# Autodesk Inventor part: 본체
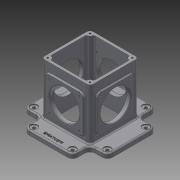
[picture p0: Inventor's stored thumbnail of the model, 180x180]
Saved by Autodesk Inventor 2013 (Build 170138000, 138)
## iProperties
Created: 2018-09
Part Number: 본체
Material: 알루미늄 6061
Document SubType Name: Modeling
Designer: mduedu
Density: 2.71 g/cm^3
Mass: 1126.64 g
Surface Area: 1144.86 cm^2
Volume: 415.736 cm^3
Author: mduedu
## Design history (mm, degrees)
sketch "스케치1"
  geometry: L1 (90, 52.5)-(-90, 52.5); L2 (-90, 52.5)-(-90, -52.5); L3 (-90, -52.5)-(90, -52.5); L4 (90, -52.5)-(90, 52.5); L5 (90, 52.5)-(-90, -52.5); L6 (-90, 52.5)-(90, -52.5); L7 (-52.5, -90)-(52.5, -90); L8 (52.5, -90)-(52.5, 90); L9 (52.5, 90)-(-52.5, 90); L10 (-52.5, 90)-(-52.5, -90); L11 (-52.5, -90)-(52.5, 90); L12 (52.5, -90)-(-52.5, 90); 1 further point
  constraints: 24 end point, 4 midpoint, 4 parallel, 2 horizontal, 2 perpendicular
  dimensions: "d0" = 180 distance of L3.end L2.end; "d1" = 105 distance of L2.end L1.end; "d105" = 105 distance of L9.end L8.end; "d106" = 180 distance of L8.end L7.end
extrude "돌출1" new body sketch "스케치1" distance "d2" = 10; taper "d3" = 0 deg
fillet "모깎기16" dims "d107" = 11
sketch "스케치2"
  geometry: L1 (-52.5, -52.5)-(52.5, -52.5); L2 (52.5, -52.5)-(52.5, 52.5); L3 (52.5, 52.5)-(-52.5, 52.5); L4 (-52.5, 52.5)-(-52.5, -52.5); L5 (-52.5, -52.5)-(52.5, 52.5); L6 (52.5, -52.5)-(-52.5, 52.5); 1 further point
  constraints: 12 end point, 2 midpoint, 2 parallel, 1 horizontal, 1 perpendicular
  dimensions: "d4" = 105 distance of L3.end L2.end; "d5" = 105 distance of L2.end L1.end
extrude "돌출2" join sketch "스케치2" distance "d6" = 110; taper "d7" = 0 deg
sketch "스케치14"
  geometry: L1 (-52.5, 52.5)-(52.5, 52.5) reference; L2 (52.5, 52.5)-(52.5, -52.5) reference; L3 (52.5, -52.5)-(-52.5, -52.5) reference; L4 (-52.5, -52.5)-(-52.5, 52.5) reference; L5 (46.5, 46.5)-(-46.5, 46.5); L6 (-46.5, 46.5)-(-46.5, -46.5); L7 (-46.5, -46.5)-(46.5, -46.5); L8 (46.5, -46.5)-(46.5, 46.5); 1 further point
  constraints: 8 end point, 3 other
  dimensions: "d85" = 6 distance between parallel lines of L5 L1
extrude "돌출10" cut sketch "스케치14" stored distance "d86" = 10; taper "d87" = 0 deg
fillet "모깎기1" dims "d12" = 7
sketch "스케치15"
  geometry: A1 r 7 centre (-45.5, 45.5) between (-45.5, 52.5) and (-52.5, 45.5) reference; A2 r 7 centre (45.5, 45.5) between (52.5, 45.5) and (45.5, 52.5) reference; A3 r 7 centre (45.5, -45.5) between (45.5, -52.5) and (52.5, -45.5) reference; A4 r 7 centre (-45.5, -45.5) between (-52.5, -45.5) and (-45.5, -52.5) reference; 5 further points
  constraints: 4 coincident, 4 vertical alignment, 8 other
extrude "돌출11" join sketch "스케치15" stored distance "d88" = 10; taper "d89" = 0 deg
fillet "모깎기15" dims "d90" = 3
sketch "스케치6"
  geometry: L1 (50, 20)-(130, 20); L2 (130, 20)-(130, 100); L3 (130, 100)-(50, 100); L4 (50, 100)-(50, 20); L5 (50, 20)-(130, 100); L6 (130, 20)-(50, 100); L7 (0, 0)-(180, 0) reference; 4 further points
  constraints: 12 end point, 4 midpoint, 2 parallel, 1 horizontal, 1 perpendicular, 1 vertical alignment
  dimensions: "d25" = 80 distance of L3.end L2.end; "d26" = 80 distance of L2.end L1.end; "d27" = 60 distance of point (90, 0) point (90, 60)
extrude "돌출6" join sketch "스케치6" distance "d28" = 3; taper "d29" = 0 deg
fillet "모깎기7" dims "d30" = 8
sketch "스케치7"
  geometry: C1 r 32.5 at (90, 60); 1 further point
  constraints: 1 centre point, 1 vertical alignment
  dimensions: "d32" = 65 diameter of C1; "d33" = 60 distance of C1.centre point (90, 0)
extrude "돌출7" cut sketch "스케치7" stored distance "d34" = 3; taper "d35" = 0 deg
fillet "모깎기9" dims "d36" = 3
sketch "스케치8"
  geometry: L1 (5.5, 10)-(85.5, 10); L2 (85.5, 10)-(85.5, 90); L3 (85.5, 90)-(5.5, 90); L4 (5.5, 90)-(5.5, 10); L5 (5.5, 10)-(85.5, 90); L6 (85.5, 10)-(5.5, 90); L7 (-7, -10)-(98, -10) reference; C1 r 32.5 at (45.5, 50); 4 further points
  constraints: 12 end point, 4 midpoint, 2 parallel, 1 centre point, 1 coincident, 1 horizontal, 1 perpendicular, 1 vertical alignment
  dimensions: "d37" = 80 distance of L3.end L2.end; "d38" = 80 distance of L2.end L1.end; "d39" = 60 distance from line of point (45.5, 50) L7; "d40" = 65 diameter of C1
extrude "돌출8" join sketch "스케치8" distance "d41" = 3; taper "d42" = 0 deg
fillet "모깎기10" dims "d43" = 8
extrude "돌출9" cut sketch "스케치8" stored distance "d44" = 3; taper "d45" = 0 deg
fillet "모깎기11" dims "d46" = 3
sketch "스케치9"
  geometry: L1 (50, 92)-(50, 28) reference; L2 (58, 20)-(122, 20) reference; L3 (130, 28)-(130, 92) reference; L4 (122, 100)-(58, 100) reference; C1 r 32.5 at (90, 60) reference; A1 r 8 centre (58, 92) between (58, 100) and (50, 92) reference; A2 r 8 centre (58, 28) between (50, 28) and (58, 20) reference; A3 r 8 centre (122, 28) between (122, 20) and (130, 28) reference; A4 r 8 centre (122, 92) between (130, 92) and (122, 100) reference; 5 further points
  constraints: 4 coincident
hole "구멍1" sketch "스케치9" at (58, 92), (122, 92), (122, 28), (58, 28) diameter "d47" = 3.242; stored, may be unused: countersink angle "d51" = 90 deg, drill point angle "d53" = 118 deg; dims "d48" = 6, "d49" = 4, "d50" = 2, "d52" = 9
sketch "스케치10"
  geometry: L1 (13.5, 10)-(77.5, 10) reference; L2 (85.5, 18)-(85.5, 82) reference; L3 (77.5, 90)-(13.5, 90) reference; L4 (5.5, 82)-(5.5, 18) reference; C1 r 32.5 at (45.5, 50) reference; A1 r 8 centre (13.5, 18) between (5.5, 18) and (13.5, 10) reference; A2 r 8 centre (77.5, 18) between (77.5, 10) and (85.5, 18) reference; A3 r 8 centre (77.5, 82) between (85.5, 82) and (77.5, 90) reference; A4 r 8 centre (13.5, 82) between (13.5, 90) and (5.5, 82) reference; 5 further points
  constraints: 4 coincident
hole "구멍2" sketch "스케치10" at (13.5, 82), (77.5, 82), (77.5, 18), (13.5, 18) diameter "d54" = 3.242; stored, may be unused: countersink angle "d58" = 90 deg, drill point angle "d60" = 118 deg; dims "d55" = 6, "d56" = 4, "d57" = 2, "d59" = 9
fillet "모깎기12" dims "d68" = 11
sketch "스케치16"
  geometry: A1 r 11 centre (-79, 41.5) between (-79, 52.5) and (-90, 41.5) reference; A2 r 11 centre (-79, -41.5) between (-90, -41.5) and (-79, -52.5) reference; A3 r 11 centre (79, 41.5) between (90, 41.5) and (79, 52.5) reference; A4 r 11 centre (79, -41.5) between (79, -52.5) and (90, -41.5) reference; A5 r 11 centre (-41.5, 79) between (-41.5, 90) and (-52.5, 79) reference; A6 r 11 centre (41.5, 79) between (52.5, 79) and (41.5, 90) reference; A7 r 11 centre (41.5, -79) between (41.5, -90) and (52.5, -79) reference; A8 r 11 centre (-41.5, -79) between (-52.5, -79) and (-41.5, -90) reference; 9 further points
  constraints: 8 coincident
hole "구멍5" sketch "스케치16" at (-79, 41.5), (79, 41.5), (79, -41.5), (-79, -41.5), (41.5, 79), (-41.5, 79), (-41.5, -79), (41.5, -79) diameter "d91" = 6.6; stored, may be unused: countersink angle "d95" = 90 deg, drill point angle "d97" = 118 deg; dims "d92" = 6, "d93" = 15, "d94" = 2, "d96" = 8
fillet "모깎기13" dims "d77" = 3
chamfer "모따기1" distance "d79" = 1; stored, may be unused: second distance "d80" = 2, angle "d81" = 45 deg
sketch "스케치17"
  geometry: A1 r 7 centre (-45.5, 45.5) between (-45.5, 52.5) and (-52.5, 45.5) reference; A2 r 7 centre (-45.5, -45.5) between (-52.5, -45.5) and (-45.5, -52.5) reference; A3 r 7 centre (45.5, -45.5) between (45.5, -52.5) and (52.5, -45.5) reference; A4 r 7 centre (45.5, 45.5) between (52.5, 45.5) and (45.5, 52.5) reference; 5 further points
  constraints: 4 coincident
hole "구멍6" sketch "스케치17" at (-45.5, 45.5), (45.5, 45.5), (45.5, -45.5), (-45.5, -45.5) diameter "d98" = 3.242; stored, may be unused: countersink angle "d102" = 90 deg, drill point angle "d104" = 118 deg; dims "d99" = 8, "d100" = 15, "d101" = 2, "d103" = 10
sketch "스케치13"
  geometry: L1 (90, -41.5)-(90, 41.5) reference; 2 further points
  constraints: 1 horizontal alignment, 1 other
  dimensions: "d82" = 11 distance from line of point (79, 0) L1
feature "엠보싱1" sketch "스케치13" dims "d0" = 180, "d1" = 105, "d83" = 0.5, "d84" = 0
node "솔리드1"
mirror "대칭1"
mirror "대칭4"
mirror "대칭2"
mirror "대칭5"
node "투영된 루프2"
node "투영된 루프3"
node "투영된 루프6"
